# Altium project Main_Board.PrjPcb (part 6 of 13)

## Sheet Power_Low_Curr.SchDoc
size A3; Organization: Altium Limited; Address1: L3, 12a Rodborough Rd; Address2: Frenchs Forest; Address3: NSW; Address4: Australia 2086
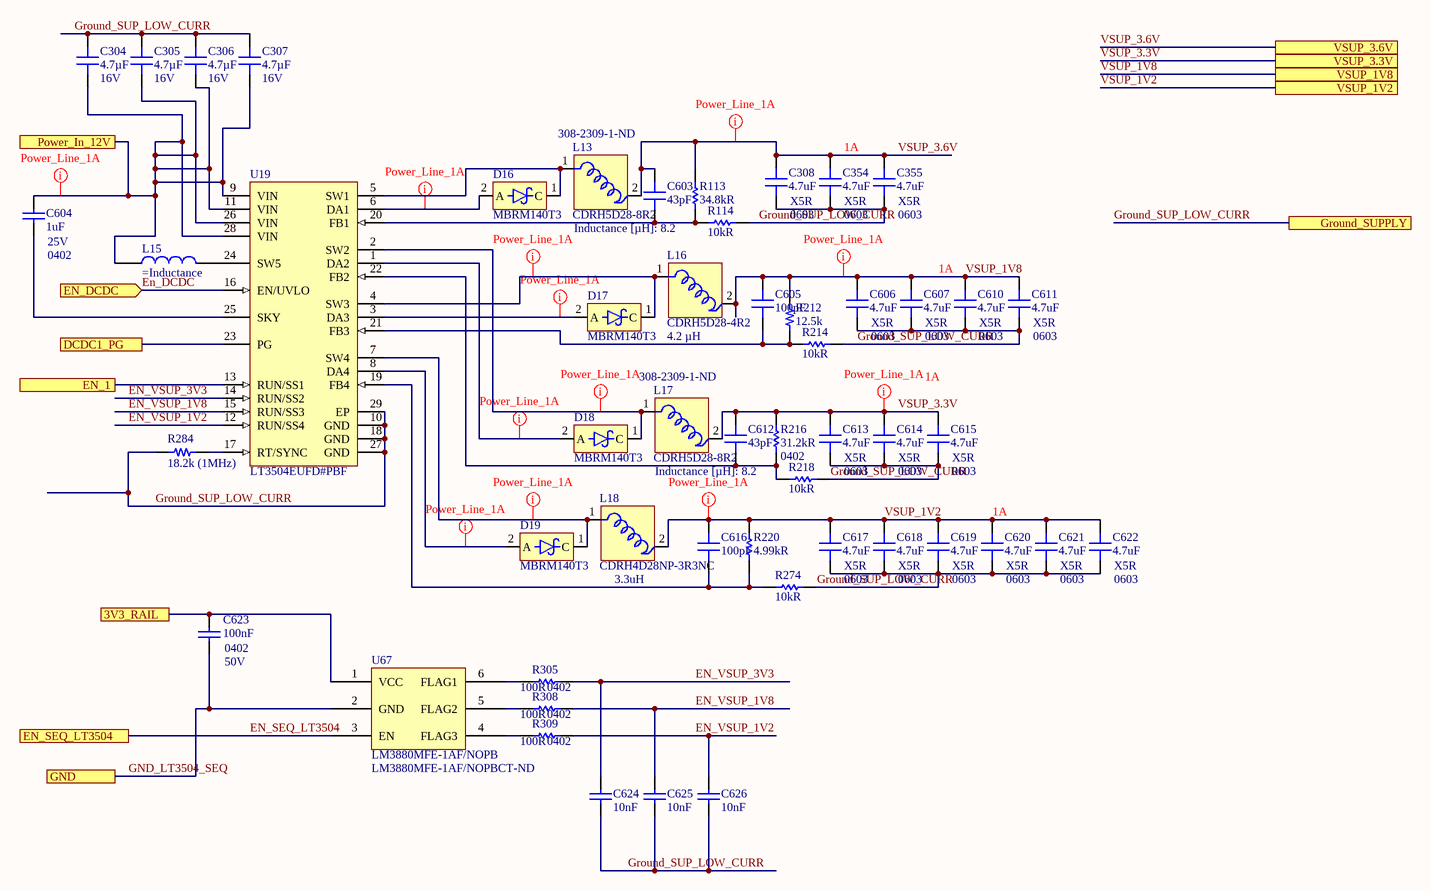
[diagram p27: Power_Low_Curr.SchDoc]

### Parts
C304  4.7µF  Parameter 1: 16V  [CAP 0603/1608 RF]
C305  4.7µF  Parameter 1: 16V  [CAP 0603/1608 RF]
C306  4.7µF  Parameter 1: 16V  [CAP 0603/1608 RF]
C307  4.7µF  Parameter 1: 16V  [CAP 0603/1608 RF]
C308  4.7uF  Case/Package: 0603  Dielectric: X5R  [CAP 0603/1608 RF]
C354  4.7uF  Case/Package: 0603  Dielectric: X5R  [CAP 0603/1608 RF]
C355  4.7uF  Case/Package: 0603  Dielectric: X5R  [CAP 0603/1608 RF]
C603  43pF  [CAP 0201/0603 KK]
C604  1uF  Case/Package: 0402  Voltage Rating: 25V  [CAP 0402/1005 KK]
C605  100pF  [CAP 0201/0603 KK]
C606  4.7uF  Case/Package: 0603  Dielectric: X5R  [CAP 0603/1608 RF]
C607  4.7uF  Case/Package: 0603  Dielectric: X5R  [CAP 0603/1608 RF]
C610  4.7uF  Case/Package: 0603  Dielectric: X5R  [CAP 0603/1608 RF]
C611  4.7uF  Case/Package: 0603  Dielectric: X5R  [CAP 0603/1608 RF]
C612  43pF  [CAP 0201/0603 KK]
C613  4.7uF  Case/Package: 0603  Dielectric: X5R  [CAP 0603/1608 RF]
C614  4.7uF  Case/Package: 0603  Dielectric: X5R  [CAP 0603/1608 RF]
C615  4.7uF  Case/Package: 0603  Dielectric: X5R  [CAP 0603/1608 RF]
C616  100pF  [CAP 0201/0603 KK]
C617  4.7uF  Case/Package: 0603  Dielectric: X5R  [CAP 0603/1608 RF]
C618  4.7uF  Case/Package: 0603  Dielectric: X5R  [CAP 0603/1608 RF]
C619  4.7uF  Case/Package: 0603  Dielectric: X5R  [CAP 0603/1608 RF]
C620  4.7uF  Case/Package: 0603  Dielectric: X5R  [CAP 0603/1608 RF]
C621  4.7uF  Case/Package: 0603  Dielectric: X5R  [CAP 0603/1608 RF]
C622  4.7uF  Case/Package: 0603  Dielectric: X5R  [CAP 0603/1608 RF]
C623  100nF  Case Code (Imperial): 0402  Voltage: 50V  [CAP 0402/1005 KK]
C624  10nF  [CAP 0201/0603 KK]
C625  10nF  [CAP 0201/0603 KK]
C626  10nF  [CAP 0201/0603 KK]
D16  MBRM140T3  [CASE 457]
D17  MBRM140T3  [CASE 457]
D18  MBRM140T3  [CASE 457]
D19  MBRM140T3  [CASE 457]
L13  CDRH5D28-8R2  Inductance [µH]: 8.2  Supplier Part Number 1: 308-2309-1-ND  [CDRH5D28]
L15  (no value)  [FB0603]
L16  CDRH5D28-4R2  Inductance: 4.2 µH  [CDRH5D28]
L17  CDRH5D28-8R2  Inductance [µH]: 8.2  Supplier Part Number 1: 308-2309-1-ND  [CDRH5D28]
L18  CDRH4D28NP-3R3NC  Inductance: 3.3uH  [CDRH4D28NP]
R113  34.8kR  [RES 0402/1005 RF KK]
R114  10kR  [RES 0402/1005 RF KK]
R212  12.5k  [RES 0402/1005 RF KK]
R214  10kR  [RES 0402/1005 RF KK]
R216  31.2kR  Case/Package: 0402  [RES 0402/1005 RF KK]
R218  10kR  [RES 0402/1005 RF KK]
R220  4.99kR  [RES 0402/1005 RF KK]
R274  10kR  [RES 0402/1005 RF KK]
R284  18.2k (1MHz)  [RES 0402/1005 RF KK]
R305  100R  Case/Package: 0402  [RES 0402/1005 RF KK]
R308  100R  Case/Package: 0402  [RES 0402/1005 RF KK]
R309  100R  Case/Package: 0402  [RES 0402/1005 RF KK]
U19  LT3504EUFD#PBF  [LT3504]
U67  LM3880MFE-1AF/NOPB  Supplier Part Number 1: LM3880MFE-1AF/NOPBCT-ND  [LM3880-Q1]

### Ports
3V3_RAIL, DCDC1_PG, EN_1, EN_DCDC (in), EN_SEQ_LT3504, GND, Ground_SUPPLY, Power_In_12V, VSUP_1V2, VSUP_1V8, VSUP_3.3V, VSUP_3.6V

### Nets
GND_LT3504_SEQ: C304.2 C305.2 C306.2 C307.2 C308.1 C354.1 C355.1 C606.1 C607.1 C610.1 C611.1 C613.1 C614.1 C615.1 C617.1 C618.1 C619.1 C620.1 C621.1 C622.1 C623.1 C624.1 C625.1 C626.1 R114.1 R214.1 R218.1 R274.1 R284.1 U19.10(GND) U19.18(GND) U19.27(GND) U19.29(EP) U67.2(GND) ; port Ground_SUPPLY, port GND  [also labelled Ground_SUP_LOW_CURR]  [project net B503_Ground]
12V_LT3042: C304.1 C305.1 C306.1 C307.1 C604.2 L15.1 U19.9(VIN) U19.11(VIN) U19.26(VIN) U19.28(VIN) ; port Power_In_12V
En_DCDC: C623.2 U19.13(RUN/SS1) U19.16(EN/UVLO) U67.1(VCC) ; port EN_1, port 3V3_RAIL, port EN_DCDC  [project net 3V3_RAIL]
EN_SEQ_LT3504: U67.3(EN) ; port EN_SEQ_LT3504
EN_VSUP_1V2: C626.2 R309.2 U19.12(RUN/SS4)
EN_VSUP_1V8: C625.2 R308.1 U19.15(RUN/SS3)
EN_VSUP_3V3: C624.2 R305.2 U19.14(RUN/SS2)
GPIOb_12.GPIO7: U19.23(PG) ; port DCDC1_PG
VSUP_1V2: C616.2 C617.2 C618.2 C619.2 C620.2 C621.2 C622.2 L18.2 R220.2 ; port VSUP_1V2  [project net US+_Vcc_PS_DDR_504]
VSUP_1V8: C605.2 C606.2 C607.2 C610.2 C611.2 L16.2 R212.2 ; port VSUP_1V8  [project net US+_MGTVccAux]
VSUP_3.3V: C612.2 C613.2 C614.2 C615.2 L17.2 R216.1 ; port VSUP_3.3V  [project net ETH_VDDIO]
VSUP_3.6V: C308.2 C354.2 C355.2 C603.2 L13.2 R113.2 ; port VSUP_3.6V  [project net ADP1741_3.6V]
NetC603_1: C603.1 R113.1 R114.2 U19.20(FB1)
NetC604_1: C604.1 U19.25(SKY)
NetC605_1: C605.1 R212.1 R214.2 U19.21(FB3)
NetC612_1: C612.1 R216.2 R218.2 U19.22(FB2)
NetC616_1: C616.1 R220.1 R274.2 U19.19(FB4)
NetD16_1: D16.1(C) L13.1 U19.5(SW1)
NetD16_2: D16.2(A) U19.6(DA1)
NetD17_1: D17.1(C) L16.1 U19.4(SW3)
NetD17_2: D17.2(A) U19.3(DA3)
NetD18_1: D18.1(C) L17.1 U19.2(SW2)
NetD18_2: D18.2(A) U19.1(DA2)
NetD19_1: D19.1(C) L18.1 U19.7(SW4)
NetD19_2: D19.2(A) U19.8(DA4)
NetL15_2: L15.2 U19.24(SW5)
NetR284_2: R284.2 U19.17(RT/SYNC)
NetR305_1: R305.1 U67.6(FLAG1)
NetR308_2: R308.2 U67.5(FLAG2)
NetR309_1: R309.1 U67.4(FLAG3)

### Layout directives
net class Power_Line_1A: 12V_LT3042, ADP1741_3.6V, ETH_VDDIO, NetD16_2, NetD17_1, NetD17_2, NetD18_1, NetD18_2, NetD19_1, NetD19_2, US+_MGTVccAux, US+_Vcc_PS_DDR_504

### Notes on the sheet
- 1A
- (near C620) 1A

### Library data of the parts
C304-C307 = Capacitor: SMT Capacitor; Part Number: CL10A475KO8NNNC
C308 C354 C355 C606 C607 C610 C611 C613-C615 C617-C622 = Capacitor: Manufacturer: Samsung; Manufacturer Part Number: CL10A475KP8NNNC; Tolerance: 10%; Voltage Rating: 10V
C603 C612 = Capacitor: Manufacturer: Murata; Manufacturer Part Number: GRM0335C1H430GA01D; Tolerance: 2%; Voltage Rating: 50V; Dielectric: C0G
C604 = Capacitor: MURATA - GRT155R61E105KE01D - SMD Multilayer Ceramic Capacitor, 1 µF, 25 V, 0402 [1005 Metric], ± 10%, X5R, GRT Series - SMD Multilayer Ceramic Capacitor, 1 µF, 25 V, 0402 [1005 Metric], ± 10%, X5R, GRT Series
C605 C616 = Capacitor: Manufacturer: Murata; Manufacturer Part Number: GRM0335C1E101JA01D; Tolerance: 5%; Voltage Rating: 25V; Dielectric: C0G
C623 = Capacitor: CAP CER 0.1UF 50V X5R 0402; Manufacturer: Murata; Manufacturer Part Number: GRM155R61H104KE14D; Dielectric Material: Ceramic; Dissipation Factor: 0.025%; Tolerance: 10%
C624-C626 = Capacitor: CAP CER 10000PF 16V X7R 0201; Manufacturer: Murata; Manufacturer Part Number: GRM033R71C103KE14D; Tolerance: 10%
D16-D19 = MBRM140T1G
L13 L17 = CDRH5D28-8R2: Part Number: CDRH5D28NP-8R2
L15 = Inductor: Manufacturer: TDK; Manufacturer Part Number: MLZ1608N6R8LT000
L18 = CDRH4D28NP-3R3NC: Fixed Inductors 3.3uH 1.57A 30% SMD LP INDUCTOR; Manufacturer: Sumida; Core Material: Ferrite; Shielding: Shielded; DC Resistance (DCR): 49.2mR; Test Frequency: 100kHz
R113 = Resistor: Thick Film Resistors 34.8K OHM 1%; Manufacturer: Yageo; Manufacturer Part Number: RC0402FR-0734K8L; Power Rating: 62.5mW; Voltage Rating: 50V; Temperature Coefficient: 100ppm/°C; Max Power Dissipation: 63mW
R114 R214 R218 R274 = Resistor: Manufacturer 1: Yageo; Manufacturer Part Number 1: RC0402FR-0710KL; Tolerance: 1%; Temperature Coefficient: 100ppm/°C; Voltage Rating: 50V; Power Rating: 62.5mW
R212 R284 = Resistor: SMT Resistor
R216 = Resistor: Manufacturer: Vishay Dale; Manufacturer Part Number: TNPW040231K2BEED; Tolerance: 0.1%; Max Power Dissipation: 63mW; Temperature Coefficient: 25ppm/°C
R220 = Resistor: Manufacturer: Panasonic; Manufacturer Part Number: ERA-2AEB4991X; Power Rating: 62.5mW; Tolerance: 0.1%; Temperature Coefficient: 25ppm/°C; Voltage Rating: 50V; Max Power Dissipation: 63mW
R305 R308 R309 = Resistor: RES SMD 100 OHM 1% 1/16W 0402; Manufacturer: Yageo; Manufacturer Part Number: RC0402FR-07100RL; Power Rating: 62.5mW; Voltage Rating: 50V; Temperature Coefficient: 100ppm/°C
U19 = LT3504EUFD#PBF: Quad 40 V / 1 A Step-Down Switching Regulator with 100% Duty Cycle Operation, 28-pin QFN (UFD-28), -40 to 125 degC, Pb-Free; Manufacturer: Linear Technology; Number of Outputs: 4
U67 = LM3880MFE-1AF/NOPB: IC PWR SUPPLY SEQUENCER SOT23-6; Manufacturer: TI National Semiconductor; Min Supply Voltage: 2.7V; Max Supply Voltage: 5.5V; Operating Supply Current: 25uA; Number of Voltages Monitored: 3; Overvoltage Threshold: 1.4V; Undervoltage Threshold: 1V; Watchdog Timer: No

## Sheet Zasilanie_CLKDistribution.SchDoc: Zasilanie sygnału zegarowego
size A3; Organization: Altium Limited; Address1: L3, 12a Rodborough Rd; Address2: Frenchs Forest; Address3: NSW; Address4: Australia 2086
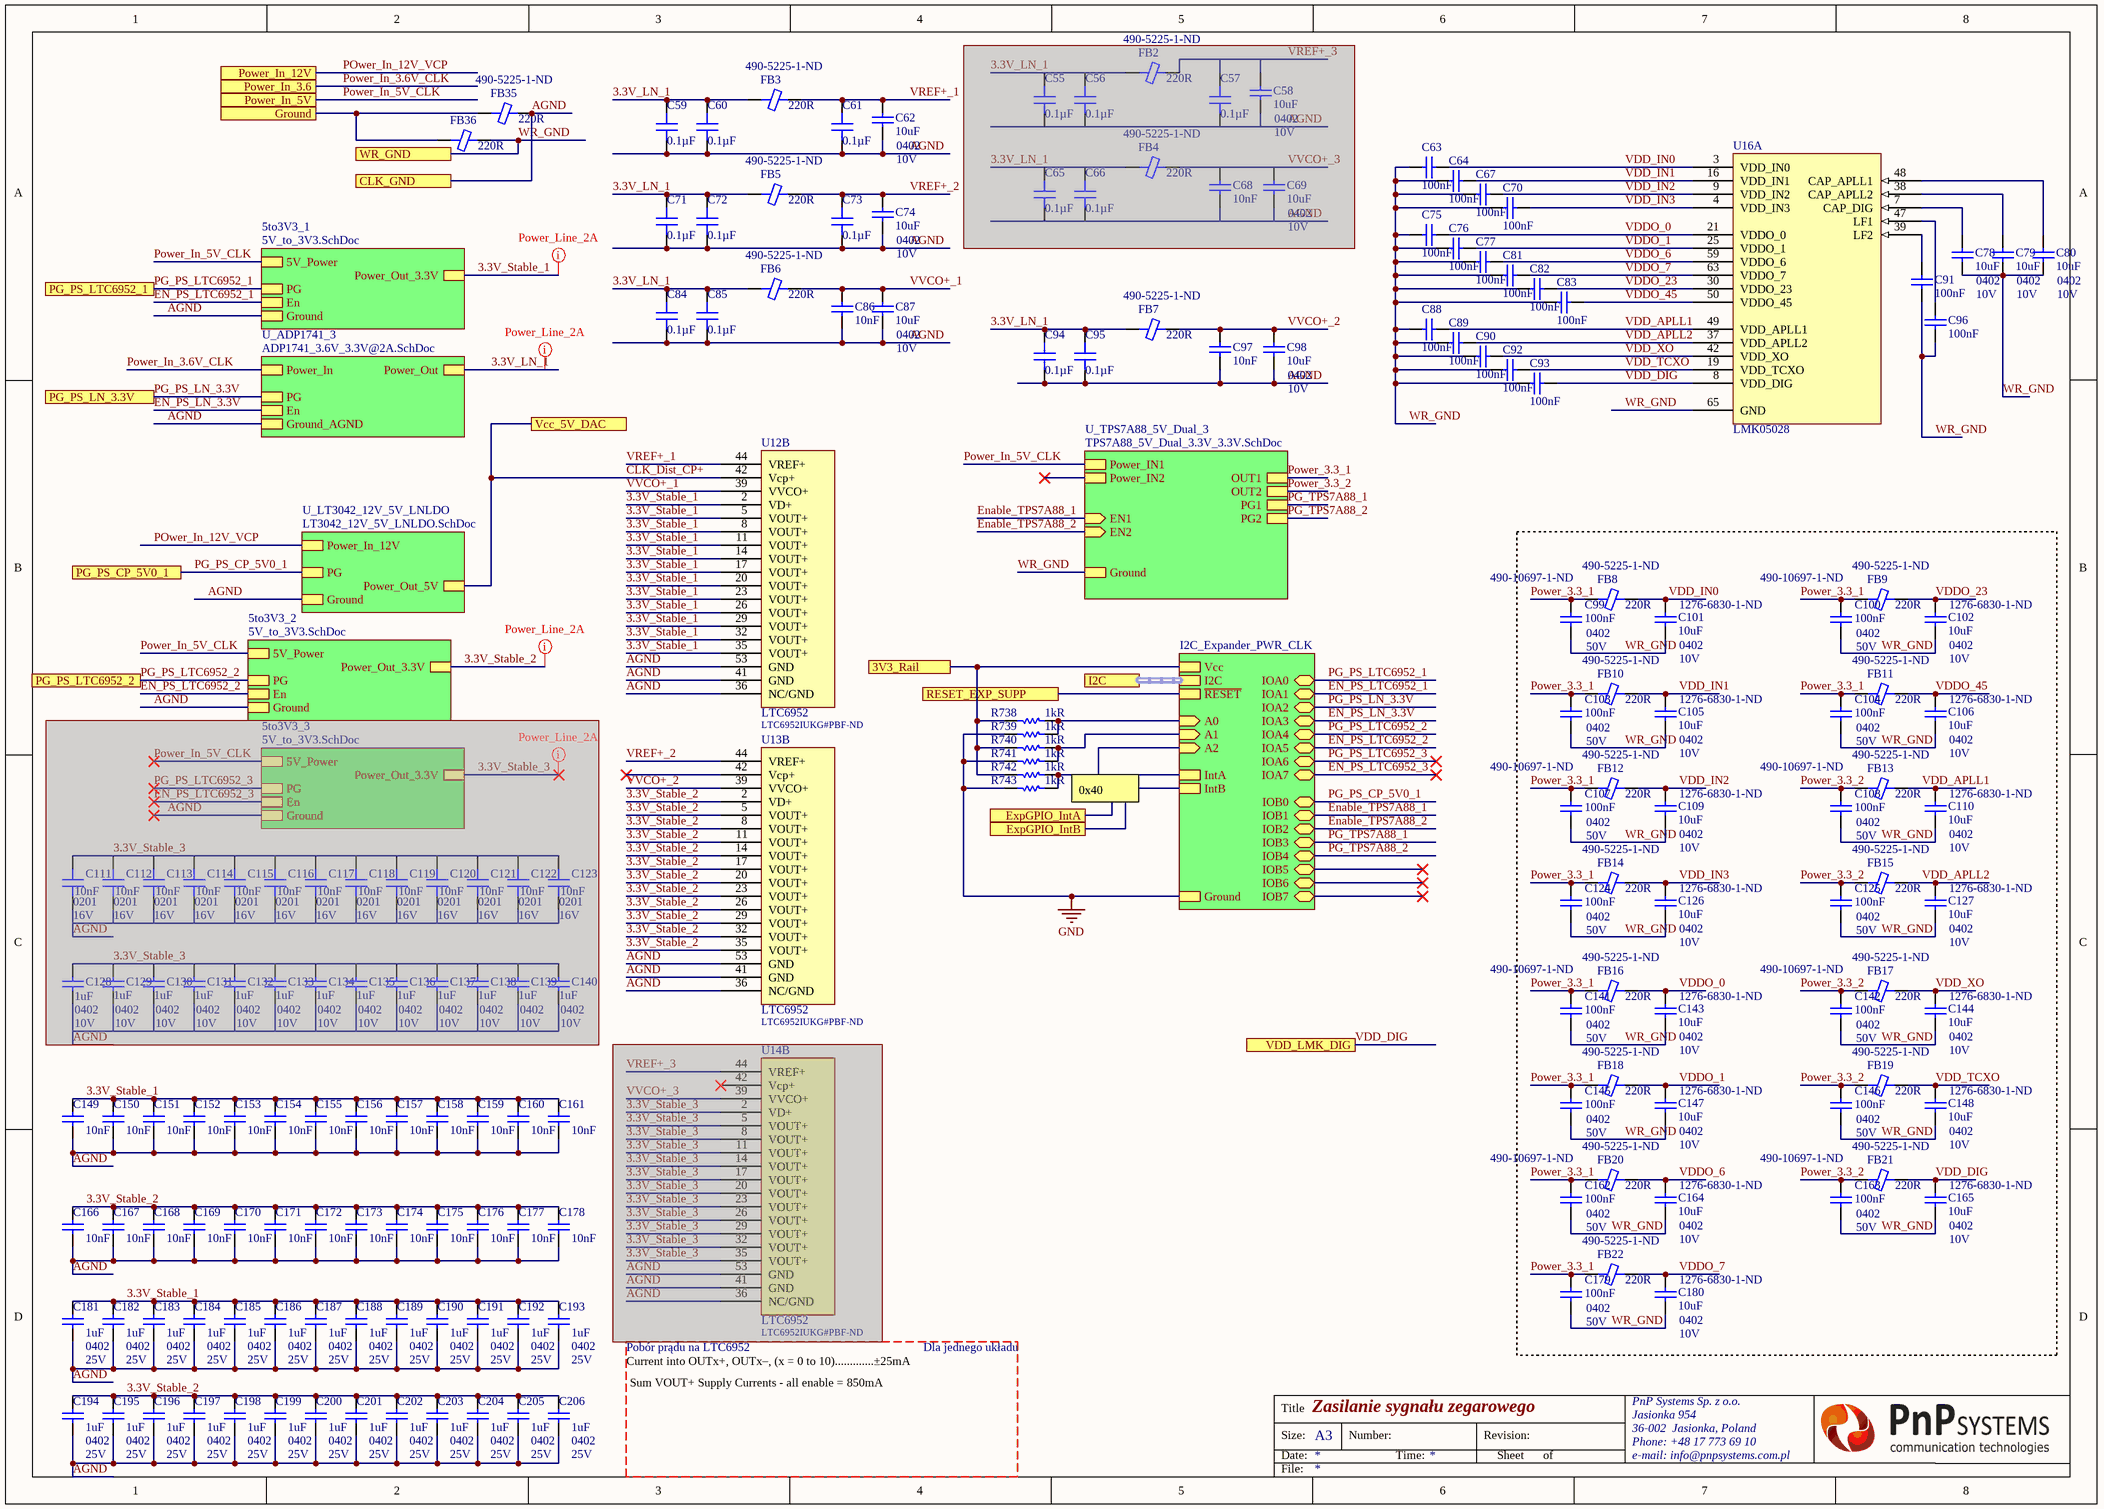
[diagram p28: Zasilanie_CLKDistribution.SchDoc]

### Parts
(Parts that share a designator on the sheet are numbered #1, #2 ... from top to bottom, then left to right.)
C55#1  0.1µF  [CAP 0201/0603 KK]  (masked out: inside a compile mask, not in the netlist)
C56#1  0.1µF  [CAP 0201/0603 KK]  (masked out: inside a compile mask, not in the netlist)
C57#1  0.1µF  [CAP 0201/0603 KK]  (masked out: inside a compile mask, not in the netlist)
C58#1  10uF  Case/Package: 0402  Voltage Rating: 10V  [CAP 0402/1005 KK]  (masked out: inside a compile mask, not in the netlist)
C59  0.1µF  [CAP 0201/0603 KK]
C60  0.1µF  [CAP 0201/0603 KK]
C61  0.1µF  [CAP 0201/0603 KK]
C62  10uF  Case/Package: 0402  Voltage Rating: 10V  [CAP 0402/1005 KK]
C63  100nF  [CAP 0402/1005 KK]
C64  100nF  [CAP 0402/1005 KK]
C65#1  0.1µF  [CAP 0201/0603 KK]  (masked out: inside a compile mask, not in the netlist)
C66#1  0.1µF  [CAP 0201/0603 KK]  (masked out: inside a compile mask, not in the netlist)
C67  100nF  [CAP 0402/1005 KK]
C68#1  10nF  [CAP 0201/0603 KK]  (masked out: inside a compile mask, not in the netlist)
C69#1  10uF  Case/Package: 0402  Voltage Rating: 10V  [CAP 0402/1005 KK]  (masked out: inside a compile mask, not in the netlist)
C70  100nF  [CAP 0402/1005 KK]
C71  0.1µF  [CAP 0201/0603 KK]
C72  0.1µF  [CAP 0201/0603 KK]
C73  0.1µF  [CAP 0201/0603 KK]
C74  10uF  Case/Package: 0402  Voltage Rating: 10V  [CAP 0402/1005 KK]
C75  100nF  [CAP 0402/1005 KK]
C76  100nF  [CAP 0402/1005 KK]
C77  100nF  [CAP 0402/1005 KK]
C78  10uF  Case/Package: 0402  Voltage Rating: 10V  [CAP 0402/1005 KK]
C79  10uF  Case/Package: 0402  Voltage Rating: 10V  [CAP 0402/1005 KK]
C80  10uF  Case/Package: 0402  Voltage Rating: 10V  [CAP 0402/1005 KK]
C81  100nF  [CAP 0402/1005 KK]
C82  100nF  [CAP 0402/1005 KK]
C83  100nF  [CAP 0402/1005 KK]
C84  0.1µF  [CAP 0201/0603 KK]
C85  0.1µF  [CAP 0201/0603 KK]
C86  10nF  [CAP 0201/0603 KK]
C87  10uF  Case/Package: 0402  Voltage Rating: 10V  [CAP 0402/1005 KK]
C88  100nF  [CAP 0402/1005 KK]
C89  100nF  [CAP 0402/1005 KK]
C90  100nF  [CAP 0402/1005 KK]
C91  100nF  [CAP 0402/1005 KK]
C92  100nF  [CAP 0402/1005 KK]
C93  100nF  [CAP 0402/1005 KK]
C94  0.1µF  [CAP 0201/0603 KK]
C95  0.1µF  [CAP 0201/0603 KK]
C96  100nF  [CAP 0402/1005 KK]
C97  10nF  [CAP 0201/0603 KK]
C98  10uF  Case/Package: 0402  Voltage Rating: 10V  [CAP 0402/1005 KK]
C99  100nF  Supplier Part Number 1: 490-10697-1-ND  Case Code (Imperial): 0402  Voltage: 50V  [CAP 0402/1005 KK]
C100  100nF  Supplier Part Number 1: 490-10697-1-ND  Case Code (Imperial): 0402  Voltage: 50V  [CAP 0402/1005 KK]
C101  10uF  Supplier Part Number 1: 1276-6830-1-ND  Case/Package: 0402  Voltage Rating: 10V  [CAP 0402/1005 KK]
C102  10uF  Supplier Part Number 1: 1276-6830-1-ND  Case/Package: 0402  Voltage Rating: 10V  [CAP 0402/1005 KK]
C103  100nF  Case Code (Imperial): 0402  Voltage: 50V  [CAP 0402/1005 KK]
C104  100nF  Case Code (Imperial): 0402  Voltage: 50V  [CAP 0402/1005 KK]
C105  10uF  Supplier Part Number 1: 1276-6830-1-ND  Case/Package: 0402  Voltage Rating: 10V  [CAP 0402/1005 KK]
C106  10uF  Supplier Part Number 1: 1276-6830-1-ND  Case/Package: 0402  Voltage Rating: 10V  [CAP 0402/1005 KK]
C107  100nF  Supplier Part Number 1: 490-10697-1-ND  Case Code (Imperial): 0402  Voltage: 50V  [CAP 0402/1005 KK]
C108  100nF  Supplier Part Number 1: 490-10697-1-ND  Case Code (Imperial): 0402  Voltage: 50V  [CAP 0402/1005 KK]
C109  10uF  Supplier Part Number 1: 1276-6830-1-ND  Case/Package: 0402  Voltage Rating: 10V  [CAP 0402/1005 KK]
C110  10uF  Supplier Part Number 1: 1276-6830-1-ND  Case/Package: 0402  Voltage Rating: 10V  [CAP 0402/1005 KK]
C111#1  10nF  Case Code (Imperial): 0201  Voltage Rating (DC): 16V  [CAP 0201/0603 KK]  (masked out: inside a compile mask, not in the netlist)
C112#1  10nF  Case Code (Imperial): 0201  Voltage Rating (DC): 16V  [CAP 0201/0603 KK]  (masked out: inside a compile mask, not in the netlist)
C113#1  10nF  Case Code (Imperial): 0201  Voltage Rating (DC): 16V  [CAP 0201/0603 KK]  (masked out: inside a compile mask, not in the netlist)
C114#1  10nF  Case Code (Imperial): 0201  Voltage Rating (DC): 16V  [CAP 0201/0603 KK]  (masked out: inside a compile mask, not in the netlist)
C115#1  10nF  Case Code (Imperial): 0201  Voltage Rating (DC): 16V  [CAP 0201/0603 KK]  (masked out: inside a compile mask, not in the netlist)
C116#1  10nF  Case Code (Imperial): 0201  Voltage Rating (DC): 16V  [CAP 0201/0603 KK]  (masked out: inside a compile mask, not in the netlist)
C117#1  10nF  Case Code (Imperial): 0201  Voltage Rating (DC): 16V  [CAP 0201/0603 KK]  (masked out: inside a compile mask, not in the netlist)
C118#2  10nF  Case Code (Imperial): 0201  Voltage Rating (DC): 16V  [CAP 0201/0603 KK]  (masked out: inside a compile mask, not in the netlist)
C119#2  10nF  Case Code (Imperial): 0201  Voltage Rating (DC): 16V  [CAP 0201/0603 KK]  (masked out: inside a compile mask, not in the netlist)
C120  10nF  Case Code (Imperial): 0201  Voltage Rating (DC): 16V  [CAP 0201/0603 KK]  (masked out: inside a compile mask, not in the netlist)
C121  10nF  Case Code (Imperial): 0201  Voltage Rating (DC): 16V  [CAP 0201/0603 KK]  (masked out: inside a compile mask, not in the netlist)
C122  10nF  Case Code (Imperial): 0201  Voltage Rating (DC): 16V  [CAP 0201/0603 KK]  (masked out: inside a compile mask, not in the netlist)
C123  10nF  Case Code (Imperial): 0201  Voltage Rating (DC): 16V  [CAP 0201/0603 KK]  (masked out: inside a compile mask, not in the netlist)
C124  100nF  Case Code (Imperial): 0402  Voltage: 50V  [CAP 0402/1005 KK]
C125  100nF  Case Code (Imperial): 0402  Voltage: 50V  [CAP 0402/1005 KK]
C126  10uF  Supplier Part Number 1: 1276-6830-1-ND  Case/Package: 0402  Voltage Rating: 10V  [CAP 0402/1005 KK]
C127  10uF  Supplier Part Number 1: 1276-6830-1-ND  Case/Package: 0402  Voltage Rating: 10V  [CAP 0402/1005 KK]
C128  1uF  Case Code (Imperial): 0402  Voltage Rating: 10V  [CAP 0402/1005 KK]  (masked out: inside a compile mask, not in the netlist)
C129  1uF  Case Code (Imperial): 0402  Voltage Rating: 10V  [CAP 0402/1005 KK]  (masked out: inside a compile mask, not in the netlist)
C130  1uF  Case Code (Imperial): 0402  Voltage Rating: 10V  [CAP 0402/1005 KK]  (masked out: inside a compile mask, not in the netlist)
C131  1uF  Case Code (Imperial): 0402  Voltage Rating: 10V  [CAP 0402/1005 KK]  (masked out: inside a compile mask, not in the netlist)
C132  1uF  Case Code (Imperial): 0402  Voltage Rating: 10V  [CAP 0402/1005 KK]  (masked out: inside a compile mask, not in the netlist)
C133  1uF  Case Code (Imperial): 0402  Voltage Rating: 10V  [CAP 0402/1005 KK]  (masked out: inside a compile mask, not in the netlist)
C134  1uF  Case Code (Imperial): 0402  Voltage Rating: 10V  [CAP 0402/1005 KK]  (masked out: inside a compile mask, not in the netlist)
C135  1uF  Case Code (Imperial): 0402  Voltage Rating: 10V  [CAP 0402/1005 KK]  (masked out: inside a compile mask, not in the netlist)
C136  1uF  Case Code (Imperial): 0402  Voltage Rating: 10V  [CAP 0402/1005 KK]  (masked out: inside a compile mask, not in the netlist)
C137  1uF  Case Code (Imperial): 0402  Voltage Rating: 10V  [CAP 0402/1005 KK]  (masked out: inside a compile mask, not in the netlist)
C138  1uF  Case Code (Imperial): 0402  Voltage Rating: 10V  [CAP 0402/1005 KK]  (masked out: inside a compile mask, not in the netlist)
C139  1uF  Case Code (Imperial): 0402  Voltage Rating: 10V  [CAP 0402/1005 KK]  (masked out: inside a compile mask, not in the netlist)
C140  1uF  Case Code (Imperial): 0402  Voltage Rating: 10V  [CAP 0402/1005 KK]  (masked out: inside a compile mask, not in the netlist)
C141  100nF  Supplier Part Number 1: 490-10697-1-ND  Case Code (Imperial): 0402  Voltage: 50V  [CAP 0402/1005 KK]
C142  100nF  Supplier Part Number 1: 490-10697-1-ND  Case Code (Imperial): 0402  Voltage: 50V  [CAP 0402/1005 KK]
C143  10uF  Supplier Part Number 1: 1276-6830-1-ND  Case/Package: 0402  Voltage Rating: 10V  [CAP 0402/1005 KK]
C144  10uF  Supplier Part Number 1: 1276-6830-1-ND  Case/Package: 0402  Voltage Rating: 10V  [CAP 0402/1005 KK]
C145  100nF  Case Code (Imperial): 0402  Voltage: 50V  [CAP 0402/1005 KK]
C146  100nF  Case Code (Imperial): 0402  Voltage: 50V  [CAP 0402/1005 KK]
C147  10uF  Supplier Part Number 1: 1276-6830-1-ND  Case/Package: 0402  Voltage Rating: 10V  [CAP 0402/1005 KK]
C148  10uF  Supplier Part Number 1: 1276-6830-1-ND  Case/Package: 0402  Voltage Rating: 10V  [CAP 0402/1005 KK]
C149  10nF  [CAP 0201/0603 KK]
C150  10nF  [CAP 0201/0603 KK]
C151  10nF  [CAP 0201/0603 KK]
C152  10nF  [CAP 0201/0603 KK]
C153  10nF  [CAP 0201/0603 KK]
C154  10nF  [CAP 0201/0603 KK]
C155  10nF  [CAP 0201/0603 KK]
C156  10nF  [CAP 0201/0603 KK]
C157  10nF  [CAP 0201/0603 KK]
C158  10nF  [CAP 0201/0603 KK]
C159  10nF  [CAP 0201/0603 KK]
C160  10nF  [CAP 0201/0603 KK]
C161  10nF  [CAP 0201/0603 KK]
C162  100nF  Supplier Part Number 1: 490-10697-1-ND  Case Code (Imperial): 0402  Voltage: 50V  [CAP 0402/1005 KK]
C163  100nF  Supplier Part Number 1: 490-10697-1-ND  Case Code (Imperial): 0402  Voltage: 50V  [CAP 0402/1005 KK]
C164  10uF  Supplier Part Number 1: 1276-6830-1-ND  Case/Package: 0402  Voltage Rating: 10V  [CAP 0402/1005 KK]
C165  10uF  Supplier Part Number 1: 1276-6830-1-ND  Case/Package: 0402  Voltage Rating: 10V  [CAP 0402/1005 KK]
C166  10nF  [CAP 0201/0603 KK]
C167  10nF  [CAP 0201/0603 KK]
C168  10nF  [CAP 0201/0603 KK]
C169  10nF  [CAP 0201/0603 KK]
C170  10nF  [CAP 0201/0603 KK]
C171  10nF  [CAP 0201/0603 KK]
C172  10nF  [CAP 0201/0603 KK]
C173  10nF  [CAP 0201/0603 KK]
C174  10nF  [CAP 0201/0603 KK]
C175  10nF  [CAP 0201/0603 KK]
C176  10nF  [CAP 0201/0603 KK]
C177  10nF  [CAP 0201/0603 KK]
C178  10nF  [CAP 0201/0603 KK]
C179  100nF  Case Code (Imperial): 0402  Voltage: 50V  [CAP 0402/1005 KK]
C180  10uF  Supplier Part Number 1: 1276-6830-1-ND  Case/Package: 0402  Voltage Rating: 10V  [CAP 0402/1005 KK]
C181  1uF  Case/Package: 0402  Voltage Rating: 25V  [CAP 0402/1005 KK]
C182  1uF  Case/Package: 0402  Voltage Rating: 25V  [CAP 0402/1005 KK]
C183  1uF  Case/Package: 0402  Voltage Rating: 25V  [CAP 0402/1005 KK]
C184  1uF  Case/Package: 0402  Voltage Rating: 25V  [CAP 0402/1005 KK]
C185  1uF  Case/Package: 0402  Voltage Rating: 25V  [CAP 0402/1005 KK]
C186  1uF  Case/Package: 0402  Voltage Rating: 25V  [CAP 0402/1005 KK]
C187  1uF  Case/Package: 0402  Voltage Rating: 25V  [CAP 0402/1005 KK]
C188  1uF  Case/Package: 0402  Voltage Rating: 25V  [CAP 0402/1005 KK]
C189  1uF  Case/Package: 0402  Voltage Rating: 25V  [CAP 0402/1005 KK]
C190  1uF  Case/Package: 0402  Voltage Rating: 25V  [CAP 0402/1005 KK]
C191  1uF  Case/Package: 0402  Voltage Rating: 25V  [CAP 0402/1005 KK]
C192  1uF  Case/Package: 0402  Voltage Rating: 25V  [CAP 0402/1005 KK]
C193  1uF  Case/Package: 0402  Voltage Rating: 25V  [CAP 0402/1005 KK]
C194  1uF  Case/Package: 0402  Voltage Rating: 25V  [CAP 0402/1005 KK]
C195  1uF  Case/Package: 0402  Voltage Rating: 25V  [CAP 0402/1005 KK]
C196  1uF  Case/Package: 0402  Voltage Rating: 25V  [CAP 0402/1005 KK]
C197  1uF  Case/Package: 0402  Voltage Rating: 25V  [CAP 0402/1005 KK]
C198  1uF  Case/Package: 0402  Voltage Rating: 25V  [CAP 0402/1005 KK]
C199  1uF  Case/Package: 0402  Voltage Rating: 25V  [CAP 0402/1005 KK]
C200  1uF  Case/Package: 0402  Voltage Rating: 25V  [CAP 0402/1005 KK]
C201  1uF  Case/Package: 0402  Voltage Rating: 25V  [CAP 0402/1005 KK]
C202  1uF  Case/Package: 0402  Voltage Rating: 25V  [CAP 0402/1005 KK]
C203  1uF  Case/Package: 0402  Voltage Rating: 25V  [CAP 0402/1005 KK]
C204  1uF  Case/Package: 0402  Voltage Rating: 25V  [CAP 0402/1005 KK]
C205  1uF  Case/Package: 0402  Voltage Rating: 25V  [CAP 0402/1005 KK]
C206  1uF  Case/Package: 0402  Voltage Rating: 25V  [CAP 0402/1005 KK]
FB2  220R  Supplier Part Number 1: 490-5225-1-ND  [FER 0603/1608]  (masked out: inside a compile mask, not in the netlist)
FB3  220R  Supplier Part Number 1: 490-5225-1-ND  [FER 0603/1608]
FB4  220R  Supplier Part Number 1: 490-5225-1-ND  [FER 0603/1608]  (masked out: inside a compile mask, not in the netlist)
FB5  220R  Supplier Part Number 1: 490-5225-1-ND  [FER 0603/1608]
FB6  220R  Supplier Part Number 1: 490-5225-1-ND  [FER 0603/1608]
FB7  220R  Supplier Part Number 1: 490-5225-1-ND  [FER 0603/1608]
FB8  220R  Supplier Part Number 1: 490-5225-1-ND  [FER 0603/1608]
FB9  220R  Supplier Part Number 1: 490-5225-1-ND  [FER 0603/1608]
FB10  220R  Supplier Part Number 1: 490-5225-1-ND  [FER 0603/1608]
FB11  220R  Supplier Part Number 1: 490-5225-1-ND  [FER 0603/1608]
FB12  220R  Supplier Part Number 1: 490-5225-1-ND  [FER 0603/1608]
FB13  220R  Supplier Part Number 1: 490-5225-1-ND  [FER 0603/1608]
FB14  220R  Supplier Part Number 1: 490-5225-1-ND  [FER 0603/1608]
FB15  220R  Supplier Part Number 1: 490-5225-1-ND  [FER 0603/1608]
FB16  220R  Supplier Part Number 1: 490-5225-1-ND  [FER 0603/1608]
FB17  220R  Supplier Part Number 1: 490-5225-1-ND  [FER 0603/1608]
FB18  220R  Supplier Part Number 1: 490-5225-1-ND  [FER 0603/1608]
FB19  220R  Supplier Part Number 1: 490-5225-1-ND  [FER 0603/1608]
FB20  220R  Supplier Part Number 1: 490-5225-1-ND  [FER 0603/1608]
FB21  220R  Supplier Part Number 1: 490-5225-1-ND  [FER 0603/1608]
FB22  220R  Supplier Part Number 1: 490-5225-1-ND  [FER 0603/1608]
FB35  220R  Supplier Part Number 1: 490-5225-1-ND  [FER 0603/1608]
FB36  220R  [FER 0603/1608]
R738  1kR  [RES 0402/1005 RF KK]
R739  1kR  [RES 0402/1005 RF KK]
R740  1kR  [RES 0402/1005 RF KK]
R741  1kR  [RES 0402/1005 RF KK]
R742  1kR  [RES 0402/1005 RF KK]
R743  1kR  [RES 0402/1005 RF KK]
U12  LTC6952  Supplier Part Number 1: LTC6952IUKG#PBF-ND  [LTC6952]  (part B of 2)
U13  LTC6952  Supplier Part Number 1: LTC6952IUKG#PBF-ND  [LTC6952]  (part B of 2)
U14  LTC6952  Supplier Part Number 1: LTC6952IUKG#PBF-ND  [LTC6952]  (part B of 2)  (masked out: inside a compile mask, not in the netlist)
U16  LMK05028  [LMK05028]  (part A of 2)

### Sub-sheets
5to3V3_1 = 5V_to_3V3.SchDoc: Ground, PG, 5V_Power, En, Power_Out_3.3V
5to3V3_2 = 5V_to_3V3.SchDoc: Ground, PG, 5V_Power, En, Power_Out_3.3V
5to3V3_3 = 5V_to_3V3.SchDoc (masked out): Ground, PG, 5V_Power, En, Power_Out_3.3V
I2C_Expander_PWR_CLK = I2C_Expander.SchDoc: IOA7 (bidir), IOA3 (bidir), IOA6 (bidir), IOA1 (bidir), IOA0 (bidir), IOA5 (bidir), IOB1 (bidir), IOB2 (bidir), IOB5 (bidir), IOB6 (bidir), IOB7 (bidir), IntA, IntB, Ground, IOB4 (bidir), IOB3 (bidir), IOA2 (bidir), IOA4 (bidir), IOB0 (bidir), Vcc, ~{RESET}, I2C (harness I2C), A2 (in), A1 (in), A0 (in)
U_ADP1741_3 = ADP1741_3.6V_3.3V@2A.SchDoc: Power_Out, PG, En, Power_In, Ground_AGND
U_LT3042_12V_5V_LNLDO = LT3042_12V_5V_LNLDO.SchDoc: Power_In_12V, Ground, PG, Power_Out_5V
U_TPS7A88_5V_Dual_3 = TPS7A88_5V_Dual_3.3V_3.3V.SchDoc: Power_IN1, Power_IN2, Ground, EN1 (in), EN2 (in), PG1, PG2, OUT1, OUT2  | Noise: LOW_NOISE

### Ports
3V3_Rail, CLK_GND, ExpGPIO_IntA, ExpGPIO_IntB, Ground, I2C (harness I2C), PG_PS_CP_5V0_1, PG_PS_LN_3.3V, PG_PS_LTC6952_1, PG_PS_LTC6952_2, Power_In_3.6, Power_In_5V, Power_In_12V, RESET_EXP_SUPP, Vcc_5V_DAC, VDD_LMK_DIG, WR_GND

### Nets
GND: FB35.1 FB36.1 R739.1 R741.1 R743.1 ; port Ground, sheet I2C_Expander_PWR_CLK/Ground  [project net B503_Ground]
3.3V_LN_1: C59.2 C60.2 C71.2 C72.2 C84.2 C85.2 C94.2 C95.2 FB3.1 FB5.1 FB6.1 FB7.1 ; sheet U_ADP1741_3/Power_Out
3.3V_Stable_1: C149.2 C150.2 C151.2 C152.2 C153.2 C154.2 C155.2 C156.2 C157.2 C158.2 C159.2 C160.2 C161.2 C181.1 C182.1 C183.1 C184.1 C185.1 C186.1 C187.1 C188.1 C189.1 C190.1 C191.1 C192.1 C193.1 U12.2(VD+) U12.5(VOUT+) U12.8(VOUT+) U12.11(VOUT+) U12.14(VOUT+) U12.17(VOUT+) U12.20(VOUT+) U12.23(VOUT+) U12.26(VOUT+) U12.29(VOUT+) U12.32(VOUT+) U12.35(VOUT+) ; sheet 5to3V3_1/Power_Out_3.3V
3.3V_Stable_2: C166.2 C167.2 C168.2 C169.2 C170.2 C171.2 C172.2 C173.2 C174.2 C175.2 C176.2 C177.2 C178.2 C194.1 C195.1 C196.1 C197.1 C198.1 C199.1 C200.1 C201.1 C202.1 C203.1 C204.1 C205.1 C206.1 U13.2(VD+) U13.5(VOUT+) U13.8(VOUT+) U13.11(VOUT+) U13.14(VOUT+) U13.17(VOUT+) U13.20(VOUT+) U13.23(VOUT+) U13.26(VOUT+) U13.29(VOUT+) U13.32(VOUT+) U13.35(VOUT+) ; sheet 5to3V3_2/Power_Out_3.3V
3V3_RAIL: R738.1 R740.1 R742.1 ; port 3V3_Rail, sheet I2C_Expander_PWR_CLK/Vcc
AGND: C59.1 C60.1 C61.1 C62.1 C71.1 C72.1 C73.1 C74.1 C84.1 C85.1 C86.1 C87.1 C94.1 C95.1 C97.1 C98.1 C149.1 C150.1 C151.1 C152.1 C153.1 C154.1 C155.1 C156.1 C157.1 C158.1 C159.1 C160.1 C161.1 C166.1 C167.1 C168.1 C169.1 C170.1 C171.1 C172.1 C173.1 C174.1 C175.1 C176.1 C177.1 C178.1 C181.2 C182.2 C183.2 C184.2 C185.2 C186.2 C187.2 C188.2 C189.2 C190.2 C191.2 C192.2 C193.2 C194.2 C195.2 C196.2 C197.2 C198.2 C199.2 C200.2 C201.2 C202.2 C203.2 C204.2 C205.2 C206.2 FB35.2 U12.36(NC/GND) U12.41(GND) U12.53(GND) U13.36(NC/GND) U13.41(GND) U13.53(GND) ; port CLK_GND, sheet U_ADP1741_3/Ground_AGND, sheet 5to3V3_1/Ground, sheet 5to3V3_2/Ground, sheet U_LT3042_12V_5V_LNLDO/Ground
CLK_Dist_CP+: U12.42(Vcp+) ; port Vcc_5V_DAC, sheet U_LT3042_12V_5V_LNLDO/Power_Out_5V  [project net 5V_LN]
EN_PS_LN_3.3V: sheet U_ADP1741_3/En, sheet I2C_Expander_PWR_CLK/IOA3  [project net ADP1741_EN]
EN_PS_LTC6952_1: sheet 5to3V3_1/En, sheet I2C_Expander_PWR_CLK/IOA1
EN_PS_LTC6952_2: sheet 5to3V3_2/En, sheet I2C_Expander_PWR_CLK/IOA5
Enable_TPS7A88_1: sheet U_TPS7A88_5V_Dual_3/EN1, sheet I2C_Expander_PWR_CLK/IOB1  [project net EN1]
Enable_TPS7A88_2: sheet U_TPS7A88_5V_Dual_3/EN2, sheet I2C_Expander_PWR_CLK/IOB2  [project net EN2]
PG_PS_CP_5V0_1: port PG_PS_CP_5V0_1, sheet U_LT3042_12V_5V_LNLDO/PG, sheet I2C_Expander_PWR_CLK/IOB0  [project net PG_LT3042]
PG_PS_LN_3.3V: port PG_PS_LN_3.3V, sheet U_ADP1741_3/PG, sheet I2C_Expander_PWR_CLK/IOA2  [project net ADP1741_PG]
PG_PS_LTC6952_1: port PG_PS_LTC6952_1, sheet 5to3V3_1/PG, sheet I2C_Expander_PWR_CLK/IOA0
PG_PS_LTC6952_2: port PG_PS_LTC6952_2, sheet 5to3V3_2/PG, sheet I2C_Expander_PWR_CLK/IOA4
PG_TPS7A88_1: sheet U_TPS7A88_5V_Dual_3/PG1, sheet I2C_Expander_PWR_CLK/IOB3  [project net PG1_TPS7A8801]
PG_TPS7A88_2: sheet U_TPS7A88_5V_Dual_3/PG2, sheet I2C_Expander_PWR_CLK/IOB4  [project net PG2_TPS7A8801]
Power_3.3_1: C99.2 C100.2 C103.2 C104.2 C107.2 C124.2 C141.2 C145.2 C162.2 C179.2 FB8.1 FB9.1 FB10.1 FB11.1 FB12.1 FB14.1 FB16.1 FB18.1 FB20.1 FB22.1 ; sheet U_TPS7A88_5V_Dual_3/OUT1
Power_3.3_2: C108.2 C125.2 C142.2 C146.2 C163.2 FB13.1 FB15.1 FB17.1 FB19.1 FB21.1 ; sheet U_TPS7A88_5V_Dual_3/OUT2
Power_In_3.6V_CLK: port Power_In_3.6, sheet U_ADP1741_3/Power_In  [project net ADP1741_3.6V]
Power_In_5V_CLK: port Power_In_5V, sheet 5to3V3_1/5V_Power, sheet 5to3V3_2/5V_Power, sheet U_TPS7A88_5V_Dual_3/Power_IN1  [project net 5V_RAIL]
POwer_In_12V_VCP: port Power_In_12V, sheet U_LT3042_12V_5V_LNLDO/Power_In_12V  [project net 12V_LT3042]
PWR_ExtIO_INT2: port ExpGPIO_IntB, sheet I2C_Expander_PWR_CLK/IntB
PWR_ExtIO_INT3: port ExpGPIO_IntA, sheet I2C_Expander_PWR_CLK/IntA
VDD_APLL1: C88.1 C110.2 FB13.2 U16.49(VDD_APLL1)
VDD_APLL2: C89.1 C127.2 FB15.2 U16.37(VDD_APLL2)
VDD_DIG: C93.1 C165.2 FB21.2 U16.8(VDD_DIG) ; port VDD_LMK_DIG
VDD_IN0: C63.1 C101.2 FB8.2 U16.3(VDD_IN0)
VDD_IN1: C64.1 C105.2 FB10.2 U16.16(VDD_IN1)
VDD_IN2: C67.1 C109.2 FB12.2 U16.9(VDD_IN2)
VDD_IN3: C70.1 C126.2 FB14.2 U16.4(VDD_IN3)
VDD_TCXO: C92.1 C148.2 FB19.2 U16.19(VDD_TCXO)
VDD_XO: C90.1 C144.2 FB17.2 U16.42(VDD_XO)
VDDO_0: C75.1 C143.2 FB16.2 U16.21(VDDO_0)
VDDO_1: C76.1 C147.2 FB18.2 U16.25(VDDO_1)
VDDO_6: C77.1 C164.2 FB20.2 U16.59(VDDO_6)
VDDO_7: C81.1 C180.2 FB22.2 U16.63(VDDO_7)
VDDO_23: C82.1 C102.2 FB9.2 U16.30(VDDO_23)
VDDO_45: C83.1 C106.2 FB11.2 U16.50(VDDO_45)
VREF+_1: C61.2 C62.2 FB3.2 U12.44(VREF+)
VREF+_2: C73.2 C74.2 FB5.2 U13.44(VREF+)
VVCO+_1: C86.2 C87.2 FB6.2 U12.39(VVCO+)
VVCO+_2: C97.2 C98.2 FB7.2 U13.39(VVCO+)
WR_GND: C63.2 C64.2 C67.2 C70.2 C75.2 C76.2 C77.2 C78.1 C79.1 C80.1 C81.2 C82.2 C83.2 C88.2 C89.2 C90.2 C91.2 C92.2 C93.2 C96.2 C99.1 C100.1 C101.1 C102.1 C103.1 C104.1 C105.1 C106.1 C107.1 C108.1 C109.1 C110.1 C124.1 C125.1 C126.1 C127.1 C141.1 C142.1 C143.1 C144.1 C145.1 C146.1 C147.1 C148.1 C162.1 C163.1 C164.1 C165.1 C179.1 C180.1 FB36.2 U16.65(GND) ; port WR_GND, sheet U_TPS7A88_5V_Dual_3/Ground  [project net Ground]
NetC78_2: C78.2 U16.7(CAP_DIG)
NetC79_2: C79.2 U16.38(CAP_APLL2)
NetC80_2: C80.2 U16.48(CAP_APLL1)
NetC91_1: C91.1 U16.39(LF2)
NetC96_1: C96.1 U16.47(LF1)
NetR738_2: R738.2 R739.2 ; sheet I2C_Expander_PWR_CLK/A0
NetR740_2: R740.2 R741.2 ; sheet I2C_Expander_PWR_CLK/A1
NetR742_2: R742.2 R743.2 ; sheet I2C_Expander_PWR_CLK/A2
NetR754_1: port RESET_EXP_SUPP, sheet I2C_Expander_PWR_CLK/~{RESET}

Not connected (* = marked no-connect by the designer): U13 42(Vcp+)*

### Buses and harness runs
harness port I2C = sheet I2C_Expander_PWR_CLK/I2C

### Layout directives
net class Power_Line_2A: 3.3V_LN_1, 3.3V_Stable_1, 3.3V_Stable_2, (no net found under the mark)

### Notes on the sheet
- 0x40
- Current into OUTx+, OUTx–, (x = 0 to 10).............±25mA
- (near U14) Pobór prądu na LTC6952
- Sum VOUT+ Supply Currents - all enable = 850mA
- Dla jednego układu

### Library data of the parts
C55#1 C56#1 C57#1 C59-C61 C65#1 C66#1 C71-C73 C84 C85 C94 C95 = Capacitor: SMT Capacitor; Part Number: GRM033R61C104ME84D
C58#1 C62 C69#1 C74 C78-C80 C87 C98 C101 C102 C105 C106 C109 C110 C126 C127 C143 C144 C147 C148 C164 C165 C180 = Capacitor: CAP CER 10UF 10V X5R 0402; Manufacturer: Samsung; Manufacturer Part Number: CL05A106MP8NUB8; Tolerance: 20%
C63 C64 C67 C70 C75-C77 C81-C83 C88-C93 C96 C99 C100 C103 C104 C107 C108 C124 C125 C141 C142 C145 C146 C162 C163 C179 = Capacitor: as C623 on sheet Power_Low_Curr
C68#1 C86 C97 C149-C161 C166-C178 = Capacitor: as C624-C626 on sheet Power_Low_Curr
C111#1 C112#1 C113#1 C114#1 C115#1 C116#1 C117#1 C118#2 C119#2 C120-C123 = Capacitor: Cap Ceramic 0.01uF 16V X5R 10% SMD 0201 85C Paper T/R; Manufacturer: Yageo; Manufacturer Part Number: CC0201KRX5R7BB103
C128-C140 = Capacitor: CAP CER 1UF 10V X5R 0402; Manufacturer: Yageo; Manufacturer Part Number: CC0402KRX5R6BB105; Tolerance: 10%; Dissipation Factor: 15%
C181-C206 = Capacitor: as C604 on sheet Power_Low_Curr
FB2-FB22 FB35 FB36 = Ferrite: FERRITE BEAD 220 OHM 0603 1LN; Manufacturer: Murata; Manufacturer Part Number: BLM18SG221TN1D; Material: Ferrite,Steel; Tolerance: 25%; Max Current Rating: 2.5A; Number of Lines: 1; DC Resistance (DCR): 40mR; Test Frequency: 100MHz
R738-R743 = Resistor: PANASONIC - ERJ-2RKF1001X - SMD Chip Resistor, 0402 [1005 Metric], 1 kohm, ERJ2R Series, 50 V, Thick Film, 100 mW; Temperature Coefficient: 100ppm/°C; Tolerance: 1%; Voltage Rating (DC): 50V; Power Rating: 100mW
U12-U14 = LTC6952: Dystrybutor Zegarów; Manufacturer: Analog Devices; Manufacturer Part Number: LTC6952IUKG#PBF
U16 = LMK05028: Manufacturer Part Number: LMK05028RGCR; Manufacturer: Texas Instruments; Number of Inputs: 4; Number of Outputs: 8

## Sheet ADP1741_3.6V_3.3V@2A.SchDoc
size A4
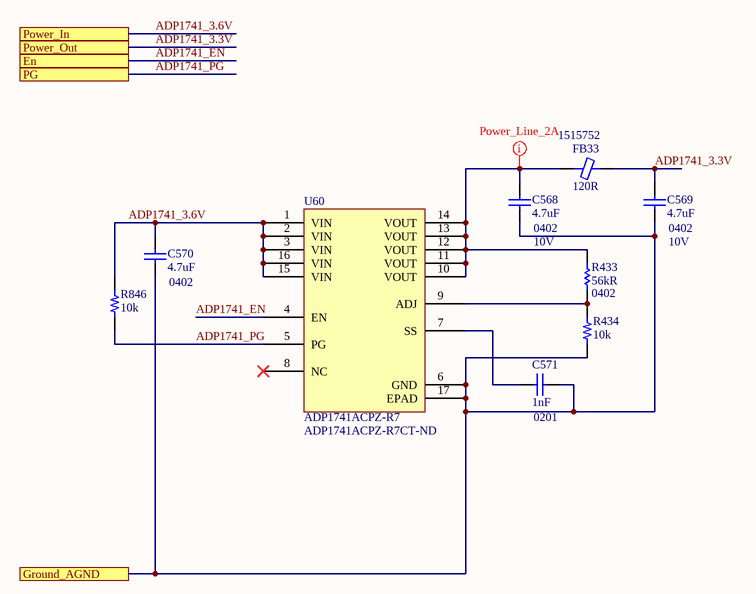
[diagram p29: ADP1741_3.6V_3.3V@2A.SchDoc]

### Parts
(Parts that share a designator on the sheet are numbered #1, #2 ... from top to bottom, then left to right.)
C568  4.7uF  Case/Package: 0402  Voltage Rating: 10V  [CAP 0402/1005 KK]
C569  4.7uF  Case/Package: 0402  Voltage Rating: 10V  [CAP 0402/1005 KK]
C570  4.7uF  Case/Package: 0402  [CAP 0402/1005 KK]
C571  1nF  Case/Package: 0201  [CAP 0201/0603 KK]
FB33  120R  Supplier Part Number 1: 1515752  [FER 0603/1608]
R433  56kR  Case/Package: 0402  [RES 0402/1005 RF KK]
R434  10k  [RES 0402/1005 RF KK]
R846#1  10k  [RES 0402/1005 RF KK]
U60  ADP1741ACPZ-R7  Supplier Part Number 1: ADP1741ACPZ-R7CT-ND  [ADP1752_1753/ADP1740_1741]

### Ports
En, Ground_AGND, PG, Power_In, Power_Out

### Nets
ADP1741_3.3V: C569.2 FB33.2 ; port Power_Out  [project net 3.3V_LN_1]
ADP1741_3.6V: C570.2 R846#1.1 U60.1(VIN) U60.2(VIN) U60.3(VIN) U60.15(VIN) U60.16(VIN) ; port Power_In
ADP1741_EN: U60.4(EN) ; port En
ADP1741_PG: R846#1.2 U60.5(PG) ; port PG
AGND: C568.1 C569.1 C570.1 C571.2 R434.2 U60.6(GND) U60.17(EPAD) ; port Ground_AGND
NetC568_2: C568.2 FB33.1 R433.2 U60.10(VOUT) U60.11(VOUT) U60.12(VOUT) U60.13(VOUT) U60.14(VOUT)
NetC571_1: C571.1 U60.7(SS)
NetR433_1: R433.1 R434.1 U60.9(ADJ)

Not connected (* = marked no-connect by the designer): U60 8(NC)*

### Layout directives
net class Power_Line_2A: NetC568_2

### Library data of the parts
C568 C569 = Capacitor: 0402 10 V 4.7 uF ±20% Tolerance X5R Multilayer Ceramic Chip Capacitor; Manufacturer: Murata; Manufacturer Part Number: GRM155R61A475MEAAD
C570 = Capacitor: 0402 10 V 4.7 uF ±20% Tolerance X5R Multilayer Ceramic Chip Capacitor; Manufacturer: Murata; Manufacturer Part Number: GRM155R61A475MEAAD; Voltage Rating: 10V
C571 = Capacitor: CAP CER 1000PF 25V X5R 0201; Manufacturer: Murata; Manufacturer Part Number: GRM033R61E102KA01D; Tolerance: 10%
FB33 = Ferrite: Ind Chip Bead 120Ohm 25% 100MHz Ferrite 3A 0603 Paper T/R; Manufacturer: Murata; Manufacturer Part Number: BLM18SG121TN1D; Material: Steel,Ferrite; DC Resistance (DCR): 25mR; Number of Circuits: 1; Shielding: Unshielded
R433 = Resistor: RES 56K OHM 1% 1/16W 0402; Manufacturer: Stackpole Electronics; Manufacturer Part Number: RMCF0402FT56K0; Max Power Dissipation: 63mW; Temperature Coefficient: 100ppm/°C
R434 R846#1 = Resistor: SMT Resistor
U60 = ADP1741ACPZ-R7: IC REG LIN POS ADJ 2A 16LFCSP; Manufacturer: Analog Devices; Output Voltage: 3V; Max Input Voltage: 3.6V; Min Input Voltage: 1.6V; Min Output Voltage: 750mV; Operating Supply Current: 1.8mA; Power Supply Rejection Ratio (PSRR): 70dB; Dropout Voltage: 160mV; Number of Outputs: 1; Min Current Limit: 2.4A; Polarity: Positive; Accuracy: 1%; Output Type: Adjustable

## Sheet 5V_to_3V3.SchDoc: 5V_to_3V3
size A4
Used 3 times, as channels PowerDistribition/Zasilanie CLK/5to3V3_1, PowerDistribition/Zasilanie CLK/5to3V3_2, U_Peripherals/Debug/5V_to_3V3_for_FTDI. Parts and nets are listed once, with the designators drawn on the sheet.
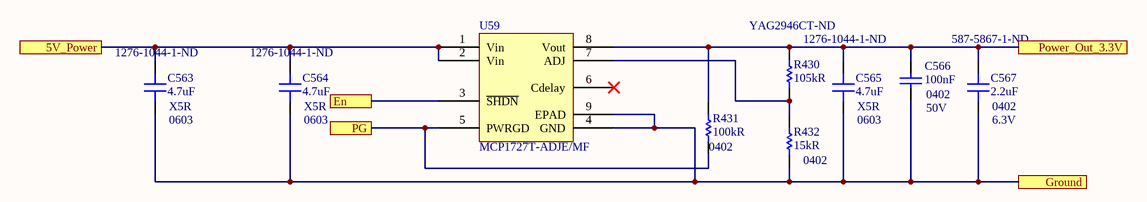
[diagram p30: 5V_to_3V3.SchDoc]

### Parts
C563  4.7uF  Supplier Part Number 1: 1276-1044-1-ND  Case/Package: 0603  Dielectric: X5R  [CAP 0603/1608 RF]
C564  4.7uF  Supplier Part Number 1: 1276-1044-1-ND  Case/Package: 0603  Dielectric: X5R  [CAP 0603/1608 RF]
C565  4.7uF  Supplier Part Number 1: 1276-1044-1-ND  Case/Package: 0603  Dielectric: X5R  [CAP 0603/1608 RF]
C566  100nF  Case Code (Imperial): 0402  Voltage: 50V  [CAP 0402/1005 KK]
C567  2.2uF  Supplier Part Number 1: 587-5867-1-ND  Case Code (Imperial): 0402  Voltage Rating: 6.3V  [CAP 0402/1005 KK]
R430  105kR  Supplier Part Number 1: YAG2946CT-ND  [RES 0402/1005 RF KK]
R431  100kR  Case/Package: 0402  [RES 0402/1005 RF KK]
R432  15kR  Case Code (Imperial): 0402  [RES 0402/1005 RF KK]
U59  MCP1727T-ADJE/MF  [MCP1727T-ADJE/MF]

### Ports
5V_Power, En, Ground, PG, Power_Out_3.3V

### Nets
5V_Power: C563.2 C564.2 U59.1(Vin) U59.2(Vin) ; port 5V_Power
En: U59.3(~{SHDN}) ; port En
Ground: C563.1 C564.1 C565.1 C566.1 C567.1 R432.1 U59.4(GND) U59.9(EPAD) ; port Ground
PG: R431.1 U59.5(PWRGD) ; port PG
Power_Out_3.3V: C565.2 C566.2 C567.2 R430.2 R431.2 U59.8(Vout) ; port Power_Out_3.3V
NetR430_1: R430.1 R432.2 U59.7(ADJ)

Not connected (* = marked no-connect by the designer): U59 6(Cdelay)*

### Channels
PowerDistribition/Zasilanie CLK/5to3V3_1: designators end in _5to3V3_1; ports 5V_Power=5V_RAIL En=EN_PS_LTC6952_1 Ground=AGND PG=PG_PS_LTC6952_1 Power_Out_3.3V=3.3V_Stable_1
PowerDistribition/Zasilanie CLK/5to3V3_2: designators end in _5to3V3_2; ports 5V_Power=5V_RAIL En=EN_PS_LTC6952_2 Ground=AGND PG=PG_PS_LTC6952_2 Power_Out_3.3V=3.3V_Stable_2
U_Peripherals/Debug/5V_to_3V3_for_FTDI: designators end in _5V_to_3V3_for_FTDI; ports 5V_Power=FTDI_5V En=FTDI_5V Ground=FTDI_GND PG=NetR431_5V_to_3V3_for_FTDI_1 Power_Out_3.3V=FTDI_VccIO

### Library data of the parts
C563-C565 = Capacitor: as C308 on sheet Power_Low_Curr
C566 = Capacitor: as C623 on sheet Power_Low_Curr
C567 = Capacitor: CAP CER 2.2UF 6.3V X5R 0402; Manufacturer: Taiyo Yuden; Manufacturer Part Number: JMK105BJ225KV-F; Tolerance: 10%
R430 = Resistor: Thick Film Resistors - SMD 105K OHM 1%; Manufacturer: Yageo; Manufacturer Part Number: RC0402FR-07105KL; Power Rating: 62.5mW; Voltage Rating: 50V; Max Power Dissipation: 63mW; Temperature Coefficient: 100ppm/°C
R431 = Resistor: Manufacturer 1: Panasonic; Manufacturer Part Number 1: ERA-2AED104X; Tolerance: 0.5%; Power Rating: 63mW; Voltage Rating: 25V; Temperature Coefficient: 25ppm/°C
R432 = Resistor: Manufacturer: Panasonic; Manufacturer Part Number: ERJ-2RKF1502X; Tolerance: 1%; Voltage Rating: 50V; Power Rating: 100mW; Temperature Coefficient: 100ppm/°C
U59 = MCP1727T-ADJE/MF: IC REG LDO ADJ 1.5A 8DFN; Manufacturer 1: Microchip; Number of Outputs: 1; Min Input Voltage: 2.3V; Max Input Voltage: 6V; Output Voltage: 5V; Dropout Voltage: 330mV; Input Bias Current: 120uA; Reference Voltage: 410mV; Polarity: Positive; Accuracy: 0.5%; Output Type: Adjustable

## Sheet LT3042_12V_5V_LNLDO.SchDoc
size A4
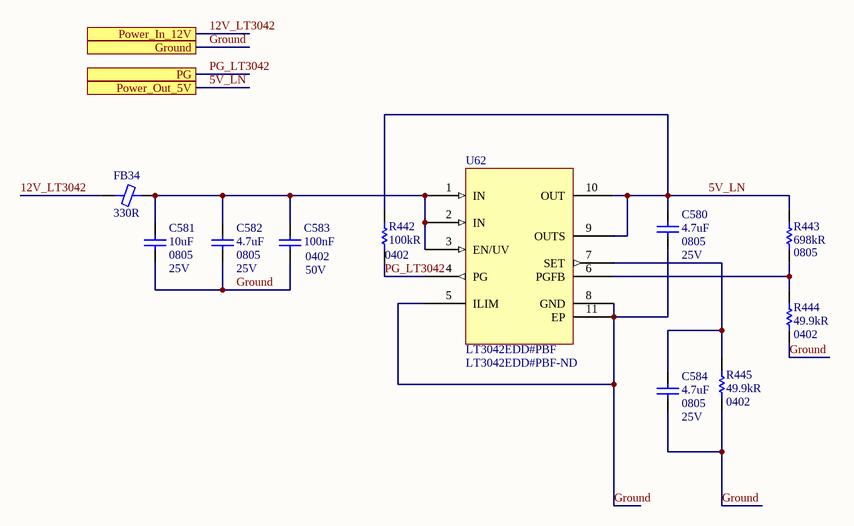
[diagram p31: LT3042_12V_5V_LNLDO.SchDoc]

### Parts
C580  4.7uF  Case/Package: 0805  Voltage Rating: 25V  [CAP 0805/2012 RF]
C581  10uF  Case/Package: 0805  Voltage Rating: 25V  [CAP 0805/2012 RF]
C582  4.7uF  Case/Package: 0805  Voltage Rating: 25V  [CAP 0805/2012 RF]
C583  100nF  Case Code (Imperial): 0402  Voltage: 50V  [CAP 0402/1005 KK]
C584  4.7uF  Case/Package: 0805  Voltage Rating: 25V  [CAP 0805/2012 RF]
FB34  330R  [FER 0603/1608]
R442  100kR  Case/Package: 0402  [RES 0402/1005 RF KK]
R443  698kR  Case/Package: 0805  [RES 0805/2012 RF]
R444  49.9kR  Case/Package: 0402  [RES 0402/1005 RF KK]
R445  49.9kR  Case/Package: 0402  [RES 0402/1005 RF KK]
U62  LT3042EDD#PBF  Supplier Part Number 1: LT3042EDD#PBF-ND  [LT3042]

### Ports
Ground, PG, Power_In_12V, Power_Out_5V

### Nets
5V_LN: C580.2 R442.2 R443.2 U62.9(OUTS) U62.10(OUT) ; port Power_Out_5V
12V_LT3042: FB34.1 ; port Power_In_12V
Ground: C580.1 C581.1 C582.1 C583.1 C584.1 R444.1 R445.1 U62.5(ILIM) U62.8(GND) U62.11(EP) ; port Ground  [project net AGND]
PG_LT3042: R442.1 U62.4(PG) ; port PG
NetC581_2: C581.2 C582.2 C583.2 FB34.2 U62.1(IN) U62.2(IN) U62.3(EN/UV)
NetC584_2: C584.2 R445.2 U62.7(SET)
NetR443_1: R443.1 R444.2 U62.6(PGFB)

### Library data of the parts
C580 C582 C584 = Capacitor: CAP CER 4.7UF 25V X5R 0805; Manufacturer: Murata; Manufacturer Part Number: GRM219R61E475KA73D; Material: Ceramic; Tolerance: 10%
C581 = Capacitor: CAP CER 10UF 25V X5R 0805; Manufacturer: KEMET; Manufacturer Part Number: C0805C106K3PACTU; Dielectric Material: Ceramic; Dissipation Factor: 10%
C583 = Capacitor: as C623 on sheet Power_Low_Curr
FB34 = Ferrite: Ferrite Beads Power Chip 330Ohm 25% 100MHz 800mA 210mOhm DCR 0603 Automotive T/R; Manufacturer: Taiyo Yuden; Manufacturer Part Number: FBMH1608HL331-T; Shielding: Unshielded; Number of Lines: 1; DC Resistance (DCR): 210mR; Max DC Current: 600mA
R442 = Resistor: as R431 on sheet 5V_to_3V3
R443 = Resistor: Panasonic ERA Series Thin Film Surface Mount Fixed Resistor 0805 Case 698k 0.1% 0.125W 25ppm/C; Manufacturer Part Number: ERA-6AEB6983V; Power Rating: 125mW; Voltage Rating: 100V; Temperature Coefficient: 25ppm/°C
R444 R445 = Resistor: Res Thin Film 0402 49.9K Ohm 0.1% 1/16W 25ppm/C Molded SMD SMD Punched Carrier T/R; Manufacturer: Panasonic; Manufacturer Part Number: ERA-2AEB4992X; Power Rating: 62.5mW; Temperature Coefficient: 25ppm/°C; Voltage Rating: 50V; Max Power Dissipation: 63mW
U62 = LT3042EDD#PBF: LINEAR TECHNOLOGY         LT3042EDD#PBF             LDO Voltage Regulator, Adjustable, 1.8V to 20V in, 350mV drop, 0V to 15V/0.2A out, DFN-10; Manufacturer: Analog Devices / Linear Technology; Output Voltage: 15V; Output Current: 200mA; Number of Regulators: 1; Min Current Limit: 220mA; Min Output Voltage: 0uV

## Sheet TPS7A88_5V_Dual_3.3V_3.3V.SchDoc
size A4
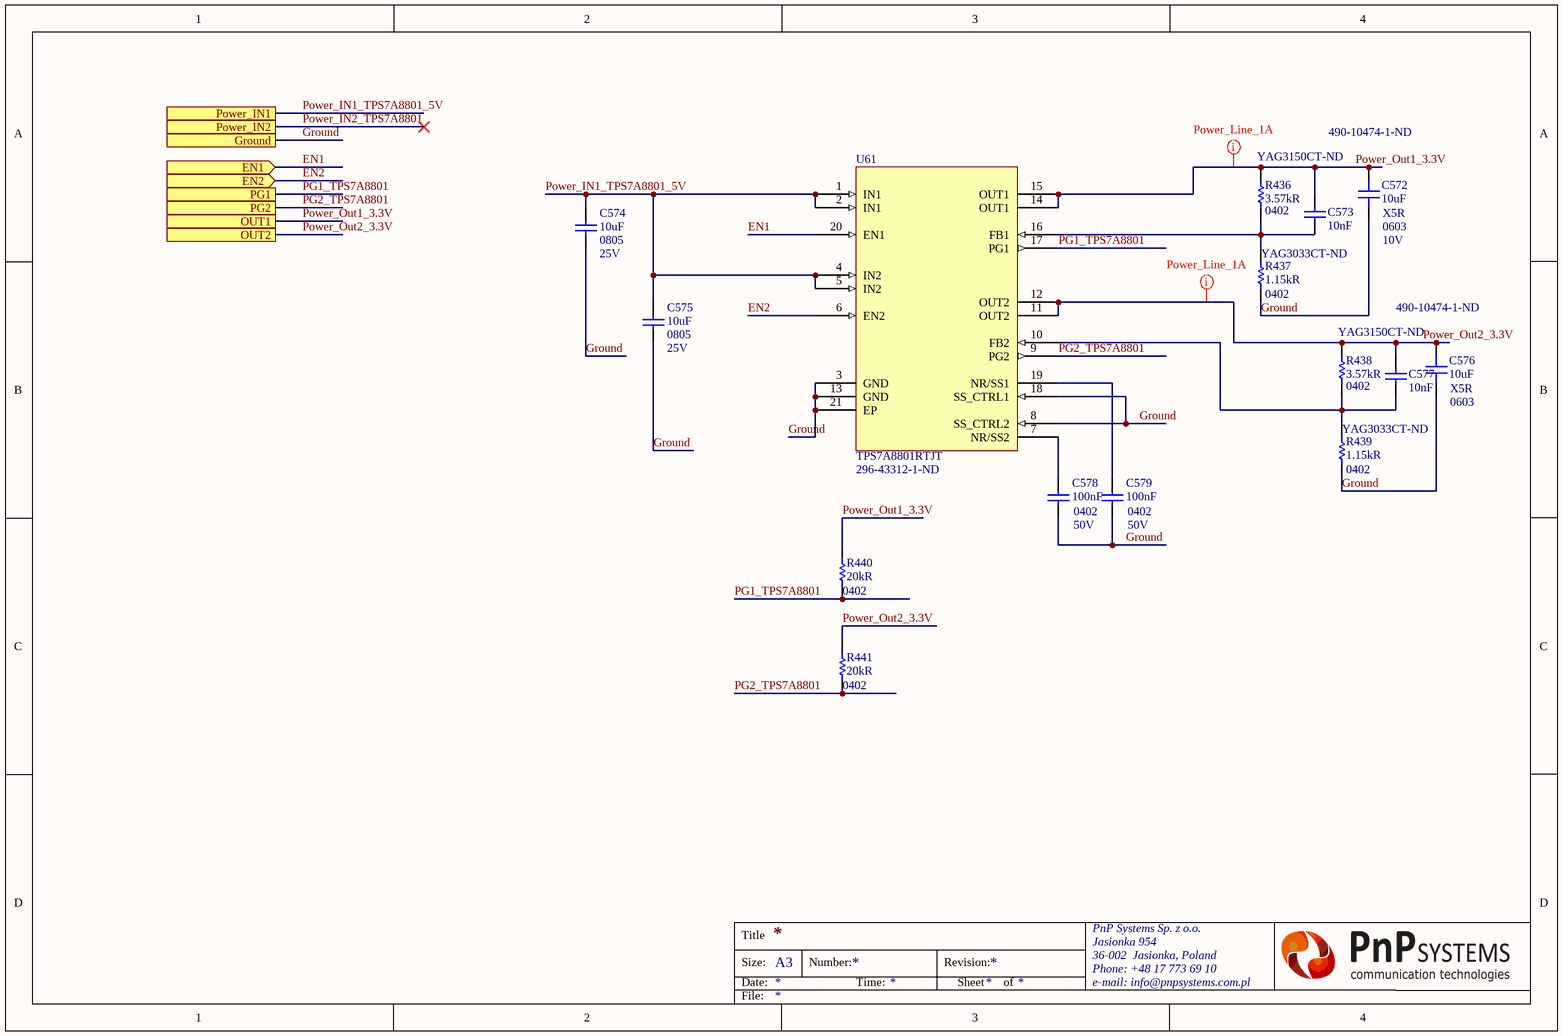
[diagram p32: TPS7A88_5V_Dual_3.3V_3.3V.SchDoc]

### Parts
C572  10uF  Supplier Part Number 1: 490-10474-1-ND  Case/Package: 0603  Dielectric: X5R  Voltage Rating: 10V  [CAP 0603/1608 RF]
C573  10nF  [CAP 0201/0603 KK]
C574  10uF  Case/Package: 0805  Voltage Rating: 25V  [CAP 0805/2012 RF]
C575  10uF  Case/Package: 0805  Voltage Rating: 25V  [CAP 0805/2012 RF]
C576  10uF  Supplier Part Number 1: 490-10474-1-ND  Case/Package: 0603  Dielectric: X5R  [CAP 0603/1608 RF]
C577  10nF  [CAP 0201/0603 KK]
C578  100nF  Case Code (Imperial): 0402  Voltage: 50V  [CAP 0402/1005 KK]
C579  100nF  Case Code (Imperial): 0402  Voltage: 50V  [CAP 0402/1005 KK]
R436  3.57kR  Supplier Part Number 1: YAG3150CT-ND  Case/Package: 0402  [RES 0402/1005 RF KK]
R437  1.15kR  Supplier Part Number 1: YAG3033CT-ND  Case/Package: 0402  [RES 0402/1005 RF KK]
R438  3.57kR  Supplier Part Number 1: YAG3150CT-ND  Case/Package: 0402  [RES 0402/1005 RF KK]
R439  1.15kR  Supplier Part Number 1: YAG3033CT-ND  Case/Package: 0402  [RES 0402/1005 RF KK]
R440  20kR  Case/Package: 0402  [RES 0402/1005 RF KK]
R441  20kR  Case/Package: 0402  [RES 0402/1005 RF KK]
U61  TPS7A8801RTJT  Supplier Part Number 1: 296-43312-1-ND  [TPS7A88]

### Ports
EN1 (in), EN2 (in), Ground, OUT1, OUT2, PG1, PG2, Power_IN1, Power_IN2

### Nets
EN1: U61.20(EN1) ; port EN1
EN2: U61.6(EN2) ; port EN2
Ground: C572.1 C574.1 C575.1 C576.1 C578.1 C579.1 R437.1 R439.1 U61.3(GND) U61.8(SS_CTRL2) U61.13(GND) U61.18(SS_CTRL1) U61.21(EP) ; port Ground
PG1_TPS7A8801: R440.2 U61.17(PG1) ; port PG1
PG2_TPS7A8801: R441.2 U61.9(PG2) ; port PG2
Power_IN1_TPS7A8801_5V: C574.2 C575.2 U61.1(IN1) U61.2(IN1) U61.4(IN2) U61.5(IN2) ; port Power_IN1  [project net 5V_RAIL]
Power_Out1_3.3V: C572.2 C573.2 R436.2 R440.1 U61.14(OUT1) U61.15(OUT1) ; port OUT1  [project net Power_3.3_1]
Power_Out2_3.3V: C576.2 C577.2 R438.2 R441.1 U61.11(OUT2) U61.12(OUT2) ; port OUT2  [project net Power_3.3_2]
NetC573_1: C573.1 R436.1 R437.2 U61.16(FB1)
NetC577_1: C577.1 R438.1 R439.2 U61.10(FB2)
NetC578_2: C578.2 U61.7(NR/SS2)
NetC579_2: C579.2 U61.19(NR/SS1)

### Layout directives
net class Power_Line_1A: Power_3.3_1, Power_3.3_2

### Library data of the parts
C572 = Capacitor: Manufacturer: Murata; Manufacturer Part Number: GRM188R61A106KE69D; Tolerance: 10%
C573 C577 = Capacitor: as C624-C626 on sheet Power_Low_Curr
C574 C575 = Capacitor: as C581 on sheet LT3042_12V_5V_LNLDO
C576 = Capacitor: Manufacturer: Murata; Manufacturer Part Number: GRM188R61A106KE69D; Tolerance: 10%; Voltage Rating: 10V
C578 C579 = Capacitor: as C623 on sheet Power_Low_Curr
R436 R438 = Resistor: Thick Film Resistors - SMD 3.57K OHM 1%; Manufacturer: Yageo; Manufacturer Part Number: RC0402FR-073K57L; Power Rating: 62.5mW; Voltage Rating: 50V; Max Power Dissipation: 63mW; Temperature Coefficient: 100ppm/°C
R437 R439 = Resistor: Res General Purpose Thick Film 0402 1.15K Ohm 1% 1/16W ±100ppm/°C Molded SMD Paper T/R; Manufacturer: Yageo; Manufacturer Part Number: RC0402FR-071K15L; Power Rating: 62.5mW; Voltage Rating: 50V; Max Power Dissipation: 63mW
R440 R441 = Resistor: Manufacturer: Panasonic; Manufacturer Part Number: ERJ-2RKF2002X; Power Rating: 100mW; Tolerance: 1%; Voltage Rating: 50V; Temperature Coefficient: 100ppm/°C
U61 = TPS7A8801RTJT: IC REG LINEAR POS ADJ 1A 20QFN; Manufacturer: Texas Instruments; Output Voltage: 5V; Number of Regulators: 2; Min Current Limit: 1.5A; Quiescent Current: 2mA; Dropout Voltage: 130mV

## Sheet I2C_Expander.SchDoc: I2C_Expander
size A3; Organization: Altium Limited; Address1: L3, 12a Rodborough Rd; Address2: Frenchs Forest; Address3: NSW; Address4: Australia 2086
Used 10 times, as channels PowerDistribition/Zasilanie CLK/I2C_Expander_PWR_CLK, PowerDistribition/I2C_Expander_PWR_Dist, Ext_GPIO/Ext_GPIO_Bank0/I2C_Expander_00, Ext_GPIO/Ext_GPIO_Bank0/I2C_Expander_01, Ext_GPIO/Ext_GPIO_Bank0/I2C_Expander_02, Ext_GPIO/Ext_GPIO_Bank1/I2C_Expander_10, Ext_GPIO/Ext_GPIO_Bank1/I2C_Expander_11, Ext_GPIO/Ext_GPIO_Bank1/I2C_Expander_12, SFP_Group+IMU/I2C_Expander_SFP, U_Expander_RESET/I2C_Expander_Main_Rst. Parts and nets are listed once, with the designators drawn on the sheet.
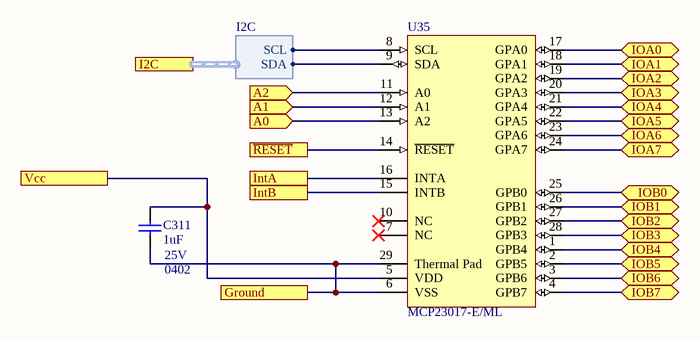
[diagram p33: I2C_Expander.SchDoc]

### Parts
C311  1uF  Case/Package: 0402  Voltage Rating: 25V  [CAP 0402/1005 KK]
U35  MCP23017-E/ML  [QFN-ML28_N]

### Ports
A0 (in), A1 (in), A2 (in), Ground, I2C (harness I2C), IntA, IntB, IOA0 (bidir), IOA1 (bidir), IOA2 (bidir), IOA3 (bidir), IOA4 (bidir), IOA5 (bidir), IOA6 (bidir), IOA7 (bidir), IOB0 (bidir), IOB1 (bidir), IOB2 (bidir), IOB3 (bidir), IOB4 (bidir), IOB5 (bidir), IOB6 (bidir), IOB7 (bidir), Vcc, ~{RESET}

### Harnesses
I2C: SCL, SDA

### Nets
A0: U35.13(A2) ; port A0
A1: U35.12(A1) ; port A1
A2: U35.11(A0) ; port A2
Ground: C311.1 U35.6(VSS) U35.29(Thermal_Pad) ; port Ground
IntA: U35.16(INTA) ; port IntA
IntB: U35.15(INTB) ; port IntB
IOA0: U35.17(GPA0) ; port IOA0
IOA1: U35.18(GPA1) ; port IOA1
IOA2: U35.19(GPA2) ; port IOA2
IOA3: U35.20(GPA3) ; port IOA3
IOA4: U35.21(GPA4) ; port IOA4
IOA5: U35.22(GPA5) ; port IOA5
IOA6: U35.23(GPA6) ; port IOA6
IOA7: U35.24(GPA7) ; port IOA7
IOB0: U35.25(GPB0) ; port IOB0
IOB1: U35.26(GPB1) ; port IOB1
IOB2: U35.27(GPB2) ; port IOB2
IOB3: U35.28(GPB3) ; port IOB3
IOB4: U35.1(GPB4) ; port IOB4
IOB5: U35.2(GPB5) ; port IOB5
IOB6: U35.3(GPB6) ; port IOB6
IOB7: U35.4(GPB7) ; port IOB7
~{RESET}: U35.14(~{RESET}) ; port ~{RESET}
Vcc: C311.2 U35.5(VDD) ; port Vcc
NetU35_8: U35.8(SCL) ; port I2C.SCL
NetU35_9: U35.9(SDA) ; port I2C.SDA

Not connected (* = marked no-connect by the designer): U35 7(NC)* 10(NC)*

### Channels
PowerDistribition/Zasilanie CLK/I2C_Expander_PWR_CLK: designators end in _I2C_Expander_PWR_CLK; ports A0=NetR738_2 A1=NetR740_2 A2=NetR742_2 Ground=B503_Ground IntA=PWR_ExtIO_INT3 IntB=PWR_ExtIO_INT2 IOA0=PG_PS_LTC6952_1 IOA1=EN_PS_LTC6952_1 IOA2=ADP1741_PG IOA3=ADP1741_EN IOA4=PG_PS_LTC6952_2 IOA5=EN_PS_LTC6952_2 IOA6=PG_PS_LTC6952_3 IOA7=EN_PS_LTC6952_3 IOB0=PG_LT3042 IOB1=EN1 IOB2=EN2 IOB3=PG1_TPS7A8801 IOB4=PG2_TPS7A8801 IOB5=NetU35_I2C_Expander_PWR_CLK_2 IOB6=NetU35_I2C_Expander_PWR_CLK_3 IOB7=NetU35_I2C_Expander_PWR_CLK_4 Vcc=3V3_RAIL ~{RESET}=NetR754_1
PowerDistribition/I2C_Expander_PWR_Dist: designators end in _I2C_Expander_PWR_Dist; ports A0=NetR455_2 A1=NetR458_2 A2=NetR462_2 Ground=B503_Ground IntA=PWR_ExtIO_INT0 IntB=PWR_ExtIO_INT1 IOA0=PWR_PowerAlert0 IOA1=PWR_PowerAlert1 IOA2=NetU35_I2C_Expander_PWR_Dist_19 IOA3=NetU35_I2C_Expander_PWR_Dist_20 IOA4=NetU35_I2C_Expander_PWR_Dist_21 IOA5=Power_MUX_Status0 IOA6=Power_MUX_Status1 IOA7=Power_MUX_Status2 IOB0=PG_3V3@14A_EXP IOB1=PG_5V@10A_EXP IOB2=PG_12@8A_EXP IOB3=PWR_Switch1_En IOB4=PWR_Switch1_Flag IOB5=PWR_Switch2_En IOB6=PWR_Switch2_Flag IOB7=PG_48_20V Vcc=3V3_RAIL ~{RESET}=PWR_ExtIO_nReset
Ext_GPIO/Ext_GPIO_Bank0/I2C_Expander_00: designators end in _I2C_Expander_00; ports A0=GPIO_Exp10_Adress0 A1=GPIO_Exp10_Adress1 A2=GPIO_Exp10_Adress2 Ground=B503_Ground IntA=GPIO_Exp10_Int0 IntB=GPIO_Exp10_Int1 IOA0=GPIOa_00.GPIO0 IOA1=GPIOa_00.GPIO1 IOA2=EN_PWR_PCIE_4 IOA3=GPIOa_00.GPIO3 IOA4=GPIOa_00.GPIO4 IOA5=GPIOa_00.GPIO5 IOA6=GPIOa_00.GPIO6 IOA7=GPIOa_00.GPIO7 IOB0=GPIOb_00.GPIO0 IOB1=GPIOb_00.GPIO1 IOB2=GPIOb_00.GPIO2 IOB3=D_05028_G4 IOB4=GPIOb_00.GPIO4 IOB5=GPIOb_00.GPIO5 IOB6=GPIOb_00.GPIO6 IOB7=GPIOb_00.GPIO7 Vcc=3V3_RAIL ~{RESET}=GPIO_Exp_Reset0
Ext_GPIO/Ext_GPIO_Bank0/I2C_Expander_01: designators end in _I2C_Expander_01; ports A0=GPIO_Exp11_Adress0 A1=GPIO_Exp11_Adress1 A2=GPIO_Exp11_Adress2 Ground=B503_Ground IntA=GPIO_Exp11_Int0 IntB=GPIO_Exp11_Int1 IOA0=GPIOa_01.GPIO0 IOA1=GPIOa_01.GPIO1 IOA2=GPIOa_01.GPIO2 IOA3=GPIOa_01.GPIO3 IOA4=GPIOa_01.GPIO4 IOA5=GPIOa_01.GPIO5 IOA6=GPIOa_01.GPIO6 IOA7=GPIOa_01.GPIO7 IOB0=GPIOb_01.GPIO0 IOB1=GPIOb_01.GPIO1 IOB2=GPIOb_01.GPIO2 IOB3=GPIOb_01.GPIO3 IOB4=GPIOb_01.GPIO4 IOB5=GPIOb_01.GPIO5 IOB6=eMMC_PG2 IOB7=eMMC_PG1 Vcc=3V3_RAIL ~{RESET}=GPIO_Exp_Reset0
Ext_GPIO/Ext_GPIO_Bank0/I2C_Expander_02: designators end in _I2C_Expander_02; ports A0=GPIO_Exp12_Adress0 A1=GPIO_Exp12_Adress1 A2=GPIO_Exp12_Adress2 Ground=B503_Ground IntA=GPIO_Exp12_Int0 IntB=GPIO_Exp12_Int1 IOA0=GPIOa_02.GPIO0 IOA1=GPIOa_02.GPIO1 IOA2=GPIOa_02.GPIO2 IOA3=GPIOa_02.GPIO3 IOA4=GPIOa_02.GPIO4 IOA5=GPIOa_02.GPIO5 IOA6=GPIOa_02.GPIO6 IOA7=EN_PWR_PCIE_3 IOB0=GPIOb_02.GPIO0 IOB1=GPIOb_02.GPIO1 IOB2=GPIOb_02.GPIO2 IOB3=GPIOb_02.GPIO3 IOB4=GPIOb_02.GPIO4 IOB5=GPIOb_02.GPIO5 IOB6=GPIOb_02.GPIO6 IOB7=GPIOb_02.GPIO7 Vcc=3V3_RAIL ~{RESET}=GPIO_Exp_Reset0
Ext_GPIO/Ext_GPIO_Bank1/I2C_Expander_10: designators end in _I2C_Expander_10; ports A0=GPIO_Exp13_Adress0 A1=GPIO_Exp13_Adress1 A2=GPIO_Exp13_Adress2 Ground=B503_Ground IntA=GPIO_Exp13_Int0 IntB=GPIO_Exp13_Int1 IOA0=En_PWRSwitch_PCIE2 IOA1=GPIOa_10.GPIO1 IOA2=GPIOa_10.GPIO2 IOA3=GPIOa_10.GPIO3 IOA4=GPIOa_10.GPIO4 IOA5=GPIOa_10.GPIO5 IOA6=GPIOa_10.GPIO6 IOA7=GPIOa_10.GPIO7 IOB0=GPIOb_10.GPIO0 IOB1=GPIOb_10.GPIO1 IOB2=En_PWRSwitch_PCIE0 IOB3=GPIOb_10.GPIO3 IOB4=GPIOb_10.GPIO4 IOB5=GPIO_ETH_EXPANDER IOB6=GPIOb_10.GPIO6 IOB7=EN_SPI_Q2 Vcc=3V3_RAIL ~{RESET}=GPIO_Exp_Reset1
Ext_GPIO/Ext_GPIO_Bank1/I2C_Expander_11: designators end in _I2C_Expander_11; ports A0=GPIO_Exp14_Adress0 A1=GPIO_Exp14_Adress1 A2=GPIO_Exp14_Adress2 Ground=B503_Ground IntA=GPIO_Exp14_Int0 IntB=GPIO_Exp14_Int1 IOA0=EN_SPI_Q1 IOA1=GPIOa_11.GPIO1 IOA2=En_PWRSwitch_PCIE1 IOA3=EN_SPI_Q0_MAIN IOA4=GPIOa_11.GPIO4 IOA5=EN_SPI_Q1_MAIN IOA6=GPIOa_11.GPIO6 IOA7=GPIOa_11.GPIO7 IOB0=EN_SPI_Q4 IOB1=GPIOb_11.GPIO1 IOB2=GPIOb_11.GPIO2 IOB3=EN_SPI_Q4_MAIN IOB4=GPIOb_11.GPIO4 IOB5=GPIOb_11.GPIO5 IOB6=GPIOb_11.GPIO6 IOB7=Charge_CAP Vcc=3V3_RAIL ~{RESET}=GPIO_Exp_Reset1
Ext_GPIO/Ext_GPIO_Bank1/I2C_Expander_12: designators end in _I2C_Expander_12; ports A0=GPIO_Exp15_Adress0 A1=GPIO_Exp15_Adress1 A2=GPIO_Exp15_Adress2 Ground=B503_Ground IntA=GPIO_Exp15_Int0 IntB=GPIO_Exp15_Int1 IOA0=FTDI_JTAG_ON_1 IOA1=FTDI_JTAG_ON_2 IOA2=FTDI_JTAG_ON_3 IOA3=FTDI_JTAG_ON_4 IOA4=D_05028_G6 IOA5=D_05028_G5 IOA6=D_05028_S1 IOA7=D_05028_S0 IOB0=D_05028_G3 IOB1=GPIOb_12.GPIO1 IOB2=GPIOb_12.GPIO2 IOB3=GPIOb_12.GPIO3 IOB4=GPIOb_12.GPIO4 IOB5=GPIOb_12.GPIO5 IOB6=EN_Detect IOB7=GPIOb_12.GPIO7 Vcc=3V3_RAIL ~{RESET}=GPIO_Exp_Reset1
SFP_Group+IMU/I2C_Expander_SFP: designators end in _I2C_Expander_SFP; ports A0=NetR475_2 A1=NetR477_2 A2=NetR479_2 Ground=B503_Ground IntA=SFP_INT0 IntB=SFP_INT1 IOA0=SFP3_TxF IOA1=SFP3_TxDis IOA2=SFP3_LOS IOA3=NetU35_I2C_Expander_SFP_20 IOA4=NetU35_I2C_Expander_SFP_21 IOA5=SFP1_TxF IOA6=SFP1_TxDis IOA7=SFP1_LOS IOB0=SFP2_TxF IOB1=SFP2_TxDis IOB2=SFP2_LOS IOB3=NetU35_I2C_Expander_SFP_28 IOB4=NetU35_I2C_Expander_SFP_1 IOB5=SFP0_TxF IOB6=SFP0_TxDis IOB7=SFP0_LOS Vcc=3V3_RAIL ~{RESET}=SFP_IO_nReset
U_Expander_RESET/I2C_Expander_Main_Rst: designators end in _I2C_Expander_Main_Rst; ports A0=NetR758_2 A1=NetR760_2 A2=NetR762_2 Ground=B503_Ground IntA=INTA_EXP_MAIN IntB=INTB_EXP_MAIN IOA0=GPIO_Exp_Reset0 IOA1=GPIO_Exp_Reset1 IOA2=GPIO_Exp_Reset2 IOA3=NetR749_1 IOA4=NetR750_1 IOA5=NetR751_1 IOA6=NetR752_1 IOA7=NetU35_I2C_Expander_Main_Rst_24 IOB0=NetR753_1 IOB1=NetR754_1 IOB2=PWR_ExtIO_nReset IOB3=SFP_IO_nReset IOB4=RST_brigde IOB5=Enable_CLK IOB6=NetSP12_I2C_Bridge_GPIO_1 IOB7=NetU35_I2C_Expander_Main_Rst_4 Vcc=3V3_RAIL ~{RESET}=MainExpReset

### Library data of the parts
C311 = Capacitor: as C604 on sheet Power_Low_Curr
U35 = MCP23017-E/ML: 16-Bit I/O Expander with Serial Interface, 28-Pin QFN, Extended Temperature; Manufacturer: Microchip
